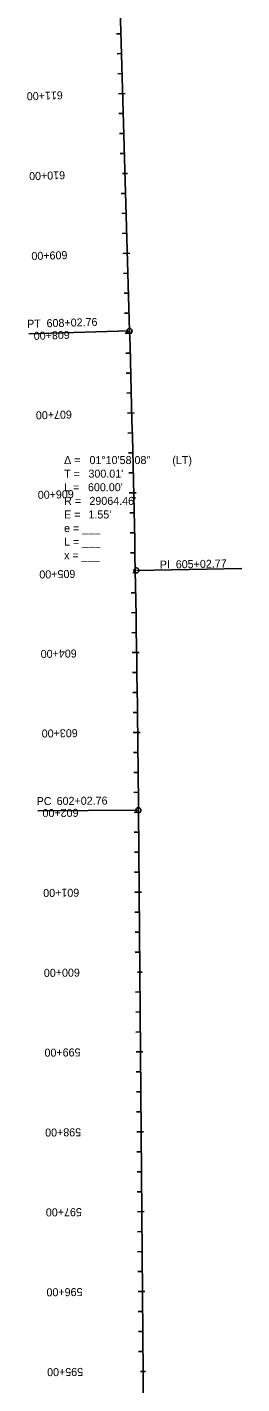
# Model space of a CAD drawing. Extents: x 23417911 to 23421158, y 6737892 to 6791804.
# Drawn here: x 23420702 to 23420970, y 6785055 to 6786753 of the extents above; entities that cross this region are included whole.
import ezdxf

# ---------------------------------------------------------------- set-up
doc = ezdxf.new("R2010")
doc.units = 0
for name, color, linetype in [('Alignment', 7, 'Continuous'), ('TextAlignment', 7, 'Continuous'), ('TextAlignmentLrg', 7, 'Continuous'), ('TextAlignmentSml', 7, 'Continuous')]:
    doc.layers.add(name, color=color, linetype=linetype)

msp = doc.modelspace()

# ---------------------------------------------------------------- linework, layer by layer
at = {"layer": 'Alignment'}
for p, q in [((23420829.7, 6786372.7), (23420747.3, 6789225.4)), ((23420829.7, 6786372.7), (23420747.3, 6789225.4)), ((23420888.7, 6779969.4), (23420840.8, 6785772.8)), ((23420888.7, 6779969.4), (23420840.8, 6785772.8))]:
    msp.add_line(p, q, dxfattribs=at)
msp.add_arc((23391777.4, 6785533.1), 29064.5, 0.47257, 1.65537, dxfattribs=at)
msp.add_arc((23391777.4, 6785533.1), 29064.5, 0.47257, 1.65537, dxfattribs=at)
at = {"layer": 'TextAlignment'}
for p, q in [((23420829.7, 6786372.7), (23420703.8, 6786369.1)), ((23420703.8, 6786369.1), (23420703.8, 6786369.1)), ((23420838.4, 6786072.8), (23420970.3, 6786075.3)), ((23420970.3, 6786075.3), (23420970.3, 6786075.3)), ((23420840.8, 6785772.8), (23420714.8, 6785771.8)), ((23420714.8, 6785771.8), (23420714.8, 6785771.8))]:
    msp.add_line(p, q, dxfattribs=at)
for centre in [(23420829.7, 6786372.7), (23420838.4, 6786072.8), (23420840.8, 6785772.8)]:
    msp.add_circle(centre, 3.12, dxfattribs=at)
at = {"layer": 'TextAlignmentLrg'}
for p, q in [((23420821.1, 6786669.8), (23420815.7, 6786669.7)), ((23420820.9, 6786569.8), (23420827.1, 6786569.9)), ((23420826.9, 6786469.9), (23420821.4, 6786469.7)), ((23420829.8, 6786369.9), (23420824.3, 6786369.8)), ((23420832.5, 6786270), (23420827, 6786269.8)), ((23420834.9, 6786170), (23420829.4, 6786169.9)), ((23420833.8, 6786070), (23420839.9, 6786070.1)), ((23420838.5, 6785970), (23420833.1, 6785970)), ((23420839.9, 6785870), (23420834.4, 6785870)), ((23420840.9, 6785770.1), (23420835.4, 6785770)), ((23420841.7, 6785670.1), (23420836.2, 6785670)), ((23420839.5, 6785570), (23420845.6, 6785570.1)), ((23420843.3, 6785470.1), (23420837.9, 6785470)), ((23420844.2, 6785370.1), (23420838.7, 6785370)), ((23420845, 6785270.1), (23420839.5, 6785270)), ((23420845.8, 6785170.1), (23420840.4, 6785170)), ((23420843.6, 6785070.1), (23420849.7, 6785070.1))]:
    msp.add_line(p, q, dxfattribs=at)
at = {"layer": 'TextAlignmentSml'}
for p, q in [((23420818.9, 6786744.8), (23420813.5, 6786744.6)), ((23420819.7, 6786719.8), (23420814.2, 6786719.6)), ((23420820.4, 6786694.8), (23420814.9, 6786694.6)), ((23420818.1, 6786669.7), (23420824.2, 6786669.9)), ((23420821.8, 6786644.8), (23420816.4, 6786644.7)), ((23420822.6, 6786619.8), (23420817.1, 6786619.7)), ((23420823.3, 6786594.8), (23420817.8, 6786594.7)), ((23420820.9, 6786569.8), (23420827.1, 6786569.9)), ((23420824.7, 6786544.9), (23420819.3, 6786544.7)), ((23420825.4, 6786519.9), (23420820, 6786519.7)), ((23420826.2, 6786494.9), (23420820.7, 6786494.7)), ((23420823.8, 6786469.8), (23420830, 6786470)), ((23420827.6, 6786444.9), (23420822.2, 6786444.7)), ((23420828.3, 6786419.9), (23420822.9, 6786419.8)), ((23420829.1, 6786394.9), (23420823.6, 6786394.8)), ((23420826.7, 6786369.9), (23420832.8, 6786370)), ((23420830.5, 6786344.9), (23420825, 6786344.8)), ((23420831.2, 6786320), (23420825.7, 6786319.8)), ((23420831.8, 6786295), (23420826.4, 6786294.8)), ((23420829.4, 6786269.9), (23420835.5, 6786270.1)), ((23420833.1, 6786245), (23420827.7, 6786244.8)), ((23420833.7, 6786220), (23420828.3, 6786219.9)), ((23420834.3, 6786195), (23420828.8, 6786194.9)), ((23420831.8, 6786169.9), (23420837.9, 6786170.1)), ((23420835.4, 6786145), (23420829.9, 6786144.9)), ((23420835.9, 6786120), (23420830.4, 6786119.9)), ((23420836.4, 6786095), (23420830.9, 6786094.9)), ((23420833.8, 6786070), (23420839.9, 6786070.1)), ((23420837.3, 6786045), (23420831.9, 6786044.9)), ((23420837.8, 6786020), (23420832.3, 6786019.9)), ((23420838.2, 6785995), (23420832.7, 6785994.9)), ((23420835.5, 6785970), (23420841.6, 6785970.1)), ((23420838.9, 6785945), (23420833.5, 6785945)), ((23420839.3, 6785920), (23420833.8, 6785920)), ((23420839.6, 6785895), (23420834.1, 6785895)), ((23420836.8, 6785870), (23420842.9, 6785870.1)), ((23420840.2, 6785845), (23420834.7, 6785845)), ((23420840.4, 6785820), (23420835, 6785820)), ((23420840.7, 6785795.1), (23420835.2, 6785795)), ((23420837.8, 6785770), (23420843.9, 6785770.1)), ((23420841.1, 6785745.1), (23420835.6, 6785745)), ((23420841.3, 6785720.1), (23420835.8, 6785720)), ((23420841.5, 6785695.1), (23420836, 6785695)), ((23420838.6, 6785670), (23420844.7, 6785670.1)), ((23420841.9, 6785645.1), (23420836.4, 6785645)), ((23420842.1, 6785620.1), (23420836.6, 6785620)), ((23420842.3, 6785595.1), (23420836.8, 6785595)), ((23420839.5, 6785570), (23420845.6, 6785570.1)), ((23420842.7, 6785545.1), (23420837.3, 6785545)), ((23420842.9, 6785520.1), (23420837.5, 6785520)), ((23420843.1, 6785495.1), (23420837.7, 6785495)), ((23420840.3, 6785470), (23420846.4, 6785470.1)), ((23420843.5, 6785445.1), (23420838.1, 6785445)), ((23420843.8, 6785420.1), (23420838.3, 6785420)), ((23420844, 6785395.1), (23420838.5, 6785395)), ((23420841.1, 6785370), (23420847.2, 6785370.1)), ((23420844.4, 6785345.1), (23420838.9, 6785345)), ((23420844.6, 6785320.1), (23420839.1, 6785320)), ((23420844.8, 6785295.1), (23420839.3, 6785295)), ((23420841.9, 6785270), (23420848, 6785270.1)), ((23420845.2, 6785245.1), (23420839.7, 6785245)), ((23420845.4, 6785220.1), (23420839.9, 6785220)), ((23420845.6, 6785195.1), (23420840.1, 6785195)), ((23420842.8, 6785170), (23420848.9, 6785170.1)), ((23420846, 6785145.1), (23420840.6, 6785145)), ((23420846.2, 6785120.1), (23420840.8, 6785120)), ((23420846.4, 6785095.1), (23420841, 6785095)), ((23420843.6, 6785070.1), (23420849.7, 6785070.1))]:
    msp.add_line(p, q, dxfattribs=at)

# ---------------------------------------------------------------- texts
at = {"layer": 'TextAlignment'}
for s, rotation, p in [('PT', 1.6554, (23420701.7, 6786376.5)), ('608+02.76', 1.6554, (23420726, 6786377.2)), ('PI ', 1.064, (23420867.7, 6786075.1)), ('605+02.77', 1.064, (23420887.7, 6786075.4)), ('PC', 0.4726, (23420713.5, 6785779)), ('602+02.76', 0.4726, (23420738.5, 6785779.2))]:
    msp.add_text(s, height=10.02, rotation=rotation, dxfattribs=at).set_placement(p)
for s, p in [('Δ = ', (23420747.8, 6786206)), ('01°10\'58.08"', (23420779.6, 6786206)), (' (LT)', (23420879.6, 6786206)), ('T = ', (23420747.8, 6786189)), ("300.01'", (23420778.3, 6786189)), ('L = ', (23420747.8, 6786172)), ("600.00'", (23420777.7, 6786172)), ('R = ', (23420747.8, 6786154.9)), ("29064.46'", (23420779.5, 6786154.9)), ('E = ', (23420747.8, 6786137.9)), ("1.55'", (23420778.3, 6786137.9)), ('e = ___ ', (23420747.8, 6786120.8)), ('L = ___', (23420747.8, 6786103.8)), ('x = ___', (23420747.8, 6786086.8))]:
    msp.add_text(s, height=10.02, dxfattribs=at).set_placement(p)
at = {"layer": 'TextAlignmentLrg'}
for s, rotation, p in [('610+00', 181.6554, (23420748.9, 6786572.7)), ('605+00', 181.0585, (23420761.8, 6786073.6)), ('600+00', 180.4726, (23420767.5, 6785574.4)), ('595+00', 180.4726, (23420771.6, 6785074.5))]:
    msp.add_text(s, height=10.02, rotation=rotation, dxfattribs=at).set_placement(p)
at = {"layer": 'TextAlignmentSml'}
for s, rotation, p in [('611+00', 181.6554, (23420746, 6786672.7)), ('610+00', 181.6554, (23420748.9, 6786572.7)), ('609+00', 181.6554, (23420751.8, 6786472.7)), ('608+00', 181.6499, (23420754.7, 6786372.8)), ('607+00', 181.4528, (23420757.4, 6786273.1)), ('606+00', 181.2557, (23420759.8, 6786173.4)), ('605+00', 181.0585, (23420761.8, 6786073.6)), ('604+00', 180.8614, (23420763.5, 6785973.9)), ('603+00', 180.6643, (23420764.8, 6785874.2)), ('602+00', 180.4726, (23420765.8, 6785774.4)), ('601+00', 180.4726, (23420766.7, 6785674.4)), ('600+00', 180.4726, (23420767.5, 6785574.4)), ('599+00', 180.4726, (23420768.3, 6785474.5)), ('598+00', 180.4726, (23420769.1, 6785374.5)), ('597+00', 180.4726, (23420770, 6785274.5)), ('596+00', 180.4726, (23420770.8, 6785174.5)), ('595+00', 180.4726, (23420771.6, 6785074.5))]:
    msp.add_text(s, height=10.02, rotation=rotation, dxfattribs=at).set_placement(p)

doc.saveas('drawing.dxf')
